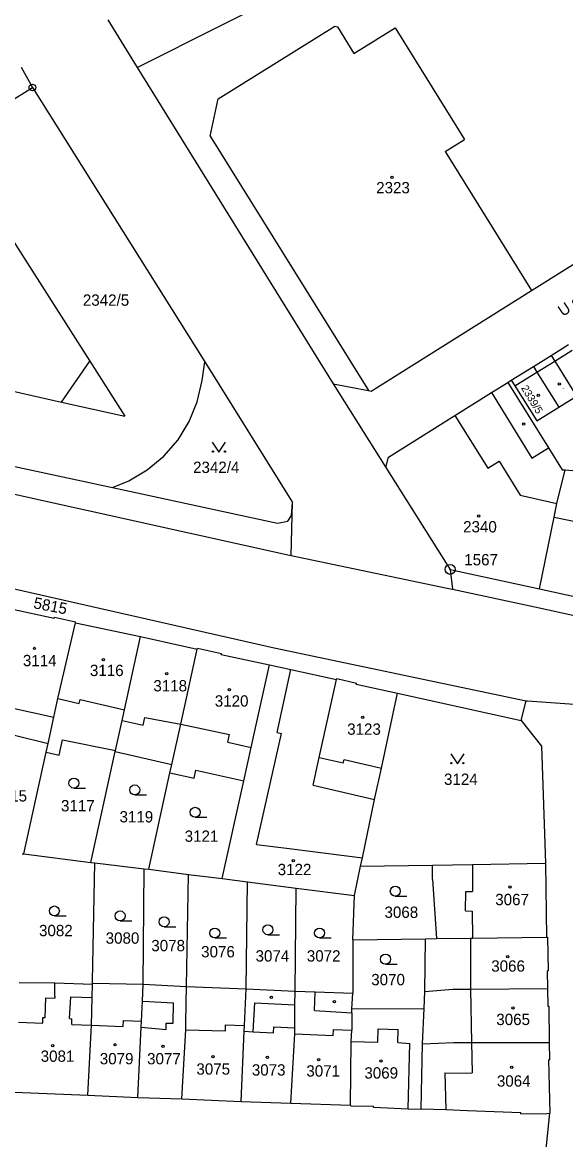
# Model space of a CAD drawing. Extents: x -735092 to -733385, y -1122435 to -1118992.
# Drawn here: x -734663.1 to -734581.5, y -1120137.2 to -1119969.3 of the extents above; entities that cross this region are included whole.
import ezdxf

# ---------------------------------------------------------------- set-up
doc = ezdxf.new("R2010")
doc.units = 0
for name, color, linetype in [('Vrstva 1', 7, 'Continuous'), ('Vrstva 15', 7, 'Continuous'), ('Vrstva 17', 7, 'Continuous'), ('Vrstva 18', 7, 'Continuous'), ('Vrstva 19', 7, 'Continuous'), ('Vrstva 25', 7, 'Continuous'), ('Vrstva 4', 7, 'Continuous')]:
    doc.layers.add(name, color=color, linetype=linetype)

msp = doc.modelspace()

# ---------------------------------------------------------------- linework, layer by layer
at = {"layer": 'Vrstva 1'}
for points in [[(-734645.81, -1119976.11), (-734620.71, -1119963.43)], [(-734650.22, -1119968.96), (-734645.81, -1119976.11)], [(-734633.69, -1119980.82), (-734616.17, -1119969.9)], [(-734616.17, -1119969.9), (-734615.74, -1119970.01)], [(-734615.74, -1119970.01), (-734613.33, -1119974.02)], [(-734610.02, -1119971.96), (-734607.12, -1119970.16)], [(-734607.12, -1119970.16), (-734596.72, -1119986.91)], [(-734613.33, -1119974.02), (-734610.02, -1119971.96)], [(-734586.64, -1120009.62), (-734530.99, -1119974.69)], [(-734663.22, -1119976.05), (-734661.56, -1119979.11)], [(-734645.81, -1119976.11), (-734642.09, -1119982.17)], [(-734665.37, -1119981.49), (-734661.56, -1119979.11)], [(-734661.56, -1119979.11), (-734635.69, -1120020.31)], [(-734642.09, -1119982.17), (-734616.43, -1120023.62)], [(-734634.88, -1119986.42), (-734633.69, -1119980.82)], [(-734634.88, -1119986.42), (-734611.09, -1120024.61)], [(-734599.58, -1119988.7), (-734596.72, -1119986.91)], [(-734599.58, -1119988.7), (-734586.64, -1120009.62)], [(-734668.88, -1119995.21), (-734652.92, -1120020.22)], [(-734610.72, -1120024.74), (-734586.64, -1120009.62)], [(-734583.7, -1120019.35), (-734581.09, -1120017.73)], [(-734759.44, -1120019.08), (-734622.96, -1120049.35)], [(-734586.37, -1120021.02), (-734583.7, -1120019.35)], [(-734583.7, -1120019.35), (-734583.17, -1120020.2)], [(-734652.92, -1120020.22), (-734647.67, -1120028.46)], [(-734636.09, -1120023.14), (-734635.69, -1120020.31)], [(-734635.69, -1120020.31), (-734622.54, -1120041.45)], [(-734589.68, -1120023.08), (-734586.37, -1120021.02)], [(-734586.37, -1120021.02), (-734585.84, -1120021.87)], [(-734583.17, -1120020.2), (-734579.89, -1120025.46)], [(-734585.84, -1120021.87), (-734582.56, -1120027.13)], [(-734667.8, -1120023.98), (-734657.17, -1120026.38)], [(-734636.81, -1120026.33), (-734636.09, -1120023.14)], [(-734616.43, -1120023.62), (-734611.09, -1120024.61)], [(-734616.43, -1120023.62), (-734608.52, -1120036.18)], [(-734592.65, -1120024.94), (-734590.18, -1120023.4)], [(-734590.18, -1120023.4), (-734589.68, -1120023.08)], [(-734590.18, -1120023.4), (-734584.08, -1120033.24)], [(-734589.68, -1120023.08), (-734589.15, -1120023.93)], [(-734589.15, -1120023.93), (-734585.87, -1120029.19)], [(-734712.66, -1120025.63), (-734649.52, -1120039.21)], [(-734611.09, -1120024.61), (-734610.72, -1120024.74)], [(-734598.14, -1120028.36), (-734592.65, -1120024.94)], [(-734582.56, -1120027.13), (-734579.89, -1120025.46)], [(-734657.17, -1120026.38), (-734647.67, -1120028.46)], [(-734638.05, -1120029.3), (-734636.81, -1120026.33)], [(-734585.87, -1120029.19), (-734582.56, -1120027.13)], [(-734639.68, -1120032.03), (-734638.05, -1120029.3)], [(-734608.13, -1120034.64), (-734598.14, -1120028.36)], [(-734641.82, -1120034.47), (-734639.68, -1120032.03)], [(-734644.33, -1120036.56), (-734641.82, -1120034.47)], [(-734584.08, -1120033.24), (-734582.04, -1120036.52)], [(-734608.52, -1120036.18), (-734608.13, -1120034.64)], [(-734608.52, -1120036.18), (-734599.31, -1120050.8)], [(-734647.1, -1120038.19), (-734644.33, -1120036.56)], [(-734582.86, -1120041.6), (-734581.6, -1120036.56)], [(-734582.04, -1120036.52), (-734581.6, -1120036.56)], [(-734581.6, -1120036.56), (-734569.64, -1120037.61)], [(-734649.52, -1120039.21), (-734647.1, -1120038.19)], [(-734649.52, -1120039.21), (-734624.77, -1120044.55)], [(-734622.73, -1120049.4), (-734622.54, -1120041.45)], [(-734622.69, -1120043.4), (-734622.54, -1120041.45)], [(-734583.27, -1120043.63), (-734582.86, -1120041.6)], [(-734624.77, -1120044.55), (-734623.21, -1120044.24)], [(-734623.21, -1120044.24), (-734622.69, -1120043.4)], [(-734585.45, -1120054.43), (-734583.27, -1120043.63)], [(-734622.96, -1120049.35), (-734622.73, -1120049.4)], [(-734622.73, -1120049.4), (-734599.31, -1120054.3)], [(-734683.27, -1120050.12), (-734625.28, -1120063.27)], [(-734599.31, -1120050.8), (-734598.87, -1120051.49)], [(-734598.87, -1120051.49), (-734585.45, -1120054.43)], [(-734598.87, -1120051.49), (-734598.52, -1120054.47)], [(-734599.31, -1120054.3), (-734598.52, -1120054.47)], [(-734598.52, -1120054.47), (-734586.13, -1120057.11)], [(-734585.45, -1120054.43), (-734561.99, -1120059.58)], [(-734664.74, -1120057.42), (-734658.29, -1120058.81)], [(-734586.13, -1120057.11), (-734553.31, -1120064.35)], [(-734658.29, -1120058.81), (-734658.25, -1120058.66)], [(-734658.25, -1120058.66), (-734655.07, -1120059.35)], [(-734657.73, -1120070.89), (-734655.1, -1120059.5)], [(-734655.1, -1120059.5), (-734655.07, -1120059.35)], [(-734655.1, -1120059.5), (-734645.32, -1120061.6)], [(-734647.73, -1120072.57), (-734645.32, -1120061.6)], [(-734645.32, -1120061.6), (-734636.82, -1120063.5)], [(-734639.3, -1120074.76), (-734636.82, -1120063.5)], [(-734636.82, -1120063.5), (-734636.79, -1120063.35)], [(-734636.79, -1120063.35), (-734633.18, -1120064.13)], [(-734633.21, -1120064.28), (-734633.18, -1120064.13)], [(-734633.21, -1120064.28), (-734625.98, -1120065.85)], [(-734625.28, -1120063.27), (-734587.43, -1120071.24)], [(-734628.06, -1120075.29), (-734625.98, -1120065.85)], [(-734625.98, -1120065.85), (-734622.75, -1120066.56)], [(-734622.75, -1120066.56), (-734615.9, -1120068.06)], [(-734618.5, -1120079.74), (-734615.9, -1120068.06)], [(-734615.9, -1120068.06), (-734615.87, -1120067.91)], [(-734615.87, -1120067.91), (-734612.93, -1120068.57)], [(-734612.97, -1120068.72), (-734612.93, -1120068.57)], [(-734612.97, -1120068.72), (-734606.76, -1120070.11)], [(-734658.35, -1120073.69), (-734657.73, -1120070.89)], [(-734609.15, -1120081.34), (-734606.76, -1120070.11)], [(-734606.76, -1120070.11), (-734588.2, -1120074.21)], [(-734588.2, -1120074.21), (-734587.43, -1120071.24)], [(-734587.43, -1120071.24), (-734587.27, -1120071.25)], [(-734587.27, -1120071.25), (-734572.48, -1120072.28)], [(-734648.09, -1120074.19), (-734647.73, -1120072.57)], [(-734659.21, -1120077.63), (-734658.35, -1120073.69)], [(-734649.09, -1120078.72), (-734648.09, -1120074.19)], [(-734640.64, -1120080.83), (-734639.3, -1120074.76)], [(-734588.2, -1120074.21), (-734585.16, -1120078.07)], [(-734668.96, -1120075.25), (-734659.21, -1120077.63)], [(-734628.71, -1120078.23), (-734628.06, -1120075.29)], [(-734659.5, -1120078.96), (-734659.21, -1120077.63)], [(-734657.54, -1120079.39), (-734657.04, -1120077.11)], [(-734657.04, -1120077.11), (-734649.09, -1120078.72)], [(-734585.16, -1120078.07), (-734584.53, -1120095.65)], [(-734662.86, -1120094.24), (-734659.5, -1120078.96)], [(-734659.5, -1120078.96), (-734657.54, -1120079.39)], [(-734652.78, -1120095.52), (-734649.12, -1120078.87)], [(-734649.12, -1120078.87), (-734649.09, -1120078.72)], [(-734649.12, -1120078.87), (-734640.64, -1120080.83)], [(-734629.82, -1120083.24), (-734628.71, -1120078.23)], [(-734619.43, -1120083.91), (-734618.5, -1120079.74)], [(-734640.91, -1120082.08), (-734640.64, -1120080.83)], [(-734610.19, -1120086.07), (-734609.15, -1120081.34)], [(-734644.1, -1120096.55), (-734640.91, -1120082.08)], [(-734640.91, -1120082.08), (-734637.28, -1120082.88)], [(-734637.28, -1120082.88), (-734637.02, -1120081.68)], [(-734637.02, -1120081.68), (-734629.82, -1120083.24)], [(-734633.07, -1120097.95), (-734629.82, -1120083.24)], [(-734619.43, -1120083.91), (-734610.19, -1120086.07)], [(-734612.02, -1120094.82), (-734610.19, -1120086.07)], [(-734663.11, -1120094.23), (-734662.86, -1120094.24)], [(-734662.86, -1120094.24), (-734652.78, -1120095.52)], [(-734612.29, -1120096.1), (-734612.02, -1120094.82)], [(-734652.78, -1120095.52), (-734652.19, -1120095.59)], [(-734652.53, -1120113.36), (-734652.19, -1120095.59)], [(-734652.19, -1120095.59), (-734644.76, -1120096.47)], [(-734644.93, -1120113.82), (-734644.76, -1120096.47)], [(-734644.76, -1120096.47), (-734644.1, -1120096.55)], [(-734644.1, -1120096.55), (-734638.11, -1120097.31)], [(-734613.2, -1120100.48), (-734612.29, -1120096.1)], [(-734612.29, -1120096.1), (-734601.52, -1120095.93)], [(-734601.53, -1120098.07), (-734601.52, -1120095.93)], [(-734601.52, -1120095.93), (-734595.52, -1120095.83)], [(-734595.52, -1120095.83), (-734584.53, -1120095.65)], [(-734584.53, -1120095.65), (-734584.4, -1120106.77)], [(-734638.44, -1120114.16), (-734638.11, -1120097.31)], [(-734638.11, -1120097.31), (-734633.07, -1120097.95)], [(-734633.07, -1120097.95), (-734629.26, -1120098.44)], [(-734601.53, -1120098.07), (-734600.93, -1120106.97)], [(-734629.48, -1120114.51), (-734629.26, -1120098.44)], [(-734629.26, -1120098.44), (-734624.27, -1120099.07)], [(-734624.27, -1120099.07), (-734621.99, -1120099.36)], [(-734622.13, -1120114.88), (-734621.99, -1120099.36)], [(-734621.99, -1120099.36), (-734613.2, -1120100.48)], [(-734613.47, -1120107.14), (-734613.2, -1120100.48)], [(-734613.47, -1120107.14), (-734602.57, -1120106.99)], [(-734613.47, -1120107.14), (-734613.47, -1120115.18)], [(-734602.67, -1120114.92), (-734602.57, -1120106.99)], [(-734602.57, -1120106.99), (-734600.93, -1120106.97)], [(-734600.93, -1120106.97), (-734595.81, -1120106.9)], [(-734595.81, -1120106.9), (-734595.5, -1120106.9)], [(-734595.5, -1120106.9), (-734584.4, -1120106.77)], [(-734584.4, -1120106.77), (-734584.26, -1120106.77)], [(-734584.26, -1120106.77), (-734584.17, -1120111.82)], [(-734652.54, -1120113.64), (-734652.53, -1120113.36)], [(-734584.32, -1120111.82), (-734584.26, -1120114.44)], [(-734584.32, -1120111.82), (-734584.17, -1120111.82)], [(-734663.52, -1120113.54), (-734658.19, -1120113.59)], [(-734658.19, -1120113.59), (-734652.54, -1120113.79)], [(-734652.58, -1120115.81), (-734652.54, -1120113.79)], [(-734652.54, -1120113.79), (-734652.54, -1120113.64)], [(-734652.54, -1120113.64), (-734644.93, -1120113.82)], [(-734645.05, -1120116.35), (-734644.93, -1120113.82)], [(-734644.93, -1120113.82), (-734638.44, -1120114.16)], [(-734638.47, -1120116.66), (-734638.44, -1120114.16)], [(-734638.44, -1120114.16), (-734629.48, -1120114.51)], [(-734629.73, -1120120.02), (-734629.48, -1120114.51)], [(-734629.48, -1120114.51), (-734622.13, -1120114.88)], [(-734622.15, -1120116.92), (-734622.13, -1120114.88)], [(-734622.13, -1120114.88), (-734619.14, -1120114.98)], [(-734619.14, -1120114.98), (-734613.47, -1120115.18)], [(-734602.78, -1120117.44), (-734602.67, -1120114.92)], [(-734602.67, -1120114.92), (-734598.45, -1120114.58)], [(-734598.45, -1120114.58), (-734595.79, -1120114.55)], [(-734595.79, -1120114.55), (-734584.26, -1120114.44)], [(-734584.26, -1120114.44), (-734584.2, -1120117.09)], [(-734652.66, -1120119.99), (-734652.58, -1120115.81)], [(-734645.19, -1120119.36), (-734645.05, -1120116.35)], [(-734638.51, -1120119.71), (-734638.47, -1120116.66)], [(-734613.62, -1120117.52), (-734613.47, -1120115.18)], [(-734622.18, -1120120.36), (-734622.15, -1120116.92)], [(-734613.63, -1120118.11), (-734613.62, -1120117.52)], [(-734613.63, -1120118.11), (-734613.61, -1120120.72)], [(-734613.62, -1120117.52), (-734602.78, -1120117.44)], [(-734603.01, -1120122.78), (-734602.78, -1120117.44)], [(-734584.2, -1120117.09), (-734584.05, -1120117.09)], [(-734584.05, -1120117.09), (-734583.98, -1120122.55)], [(-734653.23, -1120130.5), (-734652.66, -1120119.99)], [(-734645.23, -1120120.26), (-734645.19, -1120119.36)], [(-734638.52, -1120120.65), (-734638.51, -1120119.71)], [(-734629.77, -1120120.88), (-734629.73, -1120120.02)], [(-734645.73, -1120130.82), (-734645.23, -1120120.26)], [(-734639.14, -1120131.04), (-734638.52, -1120120.65)], [(-734630.24, -1120131.41), (-734629.77, -1120120.88)], [(-734622.77, -1120131.68), (-734622.19, -1120121.25)], [(-734622.19, -1120121.25), (-734622.18, -1120120.36)], [(-734613.69, -1120122.41), (-734613.61, -1120120.72)], [(-734613.81, -1120131.98), (-734613.69, -1120122.41)], [(-734603.19, -1120132.52), (-734603.01, -1120122.78)], [(-734603.01, -1120122.78), (-734598.31, -1120122.56)], [(-734598.31, -1120122.56), (-734595.67, -1120122.56)], [(-734595.67, -1120122.56), (-734583.98, -1120122.55)], [(-734583.98, -1120122.55), (-734583.94, -1120125.19)], [(-734584.08, -1120125.19), (-734583.88, -1120133.2)], [(-734584.08, -1120125.19), (-734583.94, -1120125.19)], [(-734664.23, -1120130.05), (-734653.23, -1120130.5)], [(-734653.23, -1120130.5), (-734645.73, -1120130.82)], [(-734645.73, -1120130.82), (-734639.14, -1120131.04)], [(-734639.14, -1120131.04), (-734630.24, -1120131.41)], [(-734630.24, -1120131.41), (-734622.77, -1120131.68)], [(-734622.77, -1120131.68), (-734613.81, -1120131.98)], [(-734613.81, -1120131.98), (-734613.76, -1120132.06)], [(-734613.76, -1120132.06), (-734610.36, -1120132.14)], [(-734610.37, -1120132.29), (-734610.36, -1120132.14)], [(-734610.37, -1120132.29), (-734605.18, -1120132.53)], [(-734605.18, -1120132.53), (-734603.19, -1120132.58)], [(-734603.19, -1120132.52), (-734599.51, -1120132.66)], [(-734603.19, -1120132.52), (-734603.19, -1120132.58)], [(-734599.51, -1120132.66), (-734596.23, -1120132.78)], [(-734596.23, -1120132.78), (-734588.23, -1120133.07)], [(-734588.24, -1120133.27), (-734588.23, -1120133.07)], [(-734588.24, -1120133.27), (-734584.36, -1120133.25)], [(-734585.56, -1120149.21), (-734583.88, -1120133.2)], [(-734584.36, -1120133.25), (-734583.88, -1120133.2)]]:
    msp.add_lwpolyline(points, dxfattribs=at)
at = {"layer": 'Vrstva 25'}
for points in [[(-734634.55, -1120032.4), (-734633.55, -1120033.9), (-734632.55, -1120032.4)], [(-734598.76, -1120079.21), (-734597.76, -1120080.71), (-734596.76, -1120079.21)], [(-734655.33, -1120084.35), (-734653.58, -1120084.35)], [(-734646.19, -1120085.37), (-734644.44, -1120085.37)], [(-734637.13, -1120088.74), (-734635.38, -1120088.74)], [(-734607.09, -1120100.59), (-734605.34, -1120100.59)], [(-734658.26, -1120103.56), (-734656.51, -1120103.56)], [(-734648.39, -1120104.3), (-734646.64, -1120104.3)], [(-734641.79, -1120105.18), (-734640.04, -1120105.18)], [(-734626.21, -1120106.38), (-734624.46, -1120106.38)], [(-734634.18, -1120106.87), (-734632.43, -1120106.87)], [(-734618.46, -1120106.87), (-734616.71, -1120106.87)], [(-734608.56, -1120110.8), (-734606.81, -1120110.8)]]:
    msp.add_lwpolyline(points, dxfattribs=at)
for centre, radius in [((-734661.56, -1119979.11), 0.499), ((-734661.56, -1119979.11), 0.0313), ((-734607.57, -1119992.61), 0.175), ((-734582.49, -1120023.63), 0.175), ((-734585.63, -1120025.37), 0.175), ((-734587.83, -1120029.67), 0.175), ((-734634.45, -1120033.8), 0.1), ((-734632.65, -1120033.8), 0.1), ((-734594.56, -1120043.47), 0.175), ((-734598.87, -1120051.49), 0.75), ((-734598.87, -1120051.49), 0.032), ((-734661.24, -1120063.38), 0.175), ((-734650.9, -1120065.04), 0.175), ((-734641.38, -1120067.17), 0.175), ((-734631.99, -1120069.56), 0.175), ((-734611.97, -1120073.72), 0.175), ((-734598.66, -1120080.61), 0.1), ((-734596.86, -1120080.61), 0.1), ((-734655.33, -1120083.6), 0.75), ((-734646.19, -1120084.62), 0.75), ((-734637.13, -1120087.99), 0.75), ((-734622.4, -1120095.23), 0.175), ((-734607.09, -1120099.84), 0.75), ((-734589.87, -1120099.2), 0.175), ((-734658.26, -1120102.81), 0.75), ((-734648.39, -1120103.55), 0.75), ((-734641.79, -1120104.43), 0.75), ((-734626.21, -1120105.63), 0.75), ((-734634.18, -1120106.12), 0.75), ((-734618.46, -1120106.12), 0.75), ((-734608.56, -1120110.05), 0.75), ((-734590.22, -1120109.67), 0.175), ((-734625.69, -1120115.79), 0.175), ((-734616.22, -1120116.45), 0.175), ((-734589.44, -1120117.38), 0.175), ((-734658.51, -1120123.05), 0.175), ((-734649.14, -1120122.92), 0.175), ((-734641.93, -1120123.16), 0.175), ((-734634.46, -1120124.71), 0.175), ((-734626.28, -1120124.78), 0.175), ((-734618.6, -1120125.14), 0.175), ((-734609.25, -1120125.34), 0.175), ((-734589.61, -1120126.29), 0.175)]:
    msp.add_circle(centre, radius, dxfattribs=at)
at = {"layer": 'Vrstva 4'}
for points in [[(-734583.17, -1120020.2), (-734580.56, -1120018.58)], [(-734657.17, -1120026.38), (-734652.92, -1120020.22)], [(-734585.84, -1120021.87), (-734583.17, -1120020.2)], [(-734589.15, -1120023.93), (-734585.84, -1120021.87)], [(-734592.65, -1120024.94), (-734586.61, -1120034.79)], [(-734598.14, -1120028.36), (-734593.18, -1120036.27)], [(-734586.61, -1120034.79), (-734584.08, -1120033.24)], [(-734593.18, -1120036.27), (-734591.49, -1120035.23)], [(-734591.49, -1120035.23), (-734588.35, -1120040.35)], [(-734588.35, -1120040.35), (-734582.86, -1120041.6)], [(-734583.27, -1120043.63), (-734577.16, -1120044.92)], [(-734624.84, -1120076), (-734622.75, -1120066.56)], [(-734657.73, -1120070.89), (-734654.52, -1120071.63)], [(-734654.52, -1120071.63), (-734654.38, -1120071.03)], [(-734654.38, -1120071.03), (-734647.73, -1120072.57)], [(-734668.15, -1120071.54), (-734658.35, -1120073.69)], [(-734648.09, -1120074.19), (-734644.91, -1120074.89)], [(-734644.91, -1120074.89), (-734644.66, -1120073.74)], [(-734644.66, -1120073.74), (-734639.3, -1120074.76)], [(-734639.3, -1120074.76), (-734631.96, -1120076.32)], [(-734632.21, -1120077.46), (-734631.96, -1120076.32)], [(-734627.92, -1120092.81), (-734624.19, -1120076.15)], [(-734624.84, -1120076), (-734624.19, -1120076.15)], [(-734632.21, -1120077.46), (-734628.71, -1120078.23)], [(-734618.5, -1120079.74), (-734614.89, -1120080.55)], [(-734614.89, -1120080.55), (-734614.78, -1120080.04)], [(-734614.78, -1120080.04), (-734609.15, -1120081.34)], [(-734627.92, -1120092.81), (-734623.04, -1120093.43)], [(-734623.04, -1120093.43), (-734612.02, -1120094.82)], [(-734595.52, -1120095.83), (-734595.51, -1120099.9)], [(-734596.54, -1120102.8), (-734596.48, -1120099.88)], [(-734596.48, -1120099.88), (-734595.51, -1120099.9)], [(-734596.54, -1120102.8), (-734595.56, -1120102.82)], [(-734595.56, -1120102.82), (-734595.5, -1120106.9)], [(-734595.81, -1120106.9), (-734595.79, -1120114.55)], [(-734658.2, -1120115.61), (-734658.19, -1120113.59)], [(-734619.24, -1120117.75), (-734619.14, -1120114.98)], [(-734595.79, -1120114.55), (-734595.67, -1120122.56)], [(-734659.65, -1120118.82), (-734659.53, -1120115.84)], [(-734659.53, -1120115.84), (-734658.19, -1120115.89)], [(-734658.2, -1120115.61), (-734658.19, -1120115.89)], [(-734655.97, -1120118.98), (-734655.81, -1120115.7)], [(-734655.81, -1120115.7), (-734652.58, -1120115.81)], [(-734645.05, -1120116.35), (-734640.38, -1120116.63)], [(-734640.42, -1120119.69), (-734640.38, -1120116.63)], [(-734628.42, -1120120.95), (-734628.19, -1120116.63)], [(-734628.19, -1120116.63), (-734622.15, -1120116.92)], [(-734619.24, -1120117.75), (-734613.63, -1120118.11)], [(-734663.63, -1120119.54), (-734660.01, -1120119.69)], [(-734660.01, -1120119.69), (-734659.97, -1120118.81)], [(-734659.97, -1120118.81), (-734659.65, -1120118.82)], [(-734655.97, -1120118.98), (-734655.63, -1120119)], [(-734655.66, -1120119.87), (-734655.63, -1120119)], [(-734655.66, -1120119.87), (-734652.66, -1120119.99)], [(-734652.66, -1120119.99), (-734647.93, -1120120.15)], [(-734647.93, -1120120.15), (-734647.9, -1120119.27)], [(-734647.9, -1120119.27), (-734645.19, -1120119.36)], [(-734641.5, -1120120.61), (-734641.49, -1120119.68)], [(-734641.49, -1120119.68), (-734640.42, -1120119.69)], [(-734632.58, -1120120.82), (-734632.55, -1120119.94)], [(-734632.55, -1120119.94), (-734629.73, -1120120.02)], [(-734645.23, -1120120.26), (-734641.5, -1120120.61)], [(-734638.52, -1120120.65), (-734632.58, -1120120.82)], [(-734629.77, -1120120.88), (-734628.42, -1120120.95)], [(-734628.42, -1120120.95), (-734625.35, -1120121.11)], [(-734625.35, -1120121.11), (-734625.31, -1120120.2)], [(-734625.31, -1120120.2), (-734622.18, -1120120.36)], [(-734622.19, -1120121.25), (-734616.41, -1120121.5)], [(-734616.41, -1120121.5), (-734616.37, -1120120.6)], [(-734616.37, -1120120.6), (-734613.61, -1120120.72)], [(-734609.71, -1120122.5), (-734609.65, -1120120.51)], [(-734609.65, -1120120.51), (-734606.67, -1120120.6)], [(-734606.73, -1120122.58), (-734606.67, -1120120.6)], [(-734613.69, -1120122.41), (-734609.71, -1120122.5)], [(-734606.73, -1120122.58), (-734604.91, -1120122.7)], [(-734605.18, -1120132.53), (-734604.91, -1120122.7)], [(-734595.67, -1120122.56), (-734595.54, -1120127.12)], [(-734599.64, -1120127.11), (-734599.51, -1120132.66)], [(-734599.64, -1120127.11), (-734596.46, -1120127.16)], [(-734596.46, -1120127.16), (-734595.54, -1120127.12)]]:
    msp.add_lwpolyline(points, dxfattribs=at)

# ---------------------------------------------------------------- texts
at = {"layer": 'Vrstva 15'}
msp.add_text('U spojky', height=1.7, rotation=33.70027, dxfattribs=at).set_placement((-734581.955, -1120013.573))
at = {"layer": 'Vrstva 17'}
msp.add_text('1567', height=1.7, dxfattribs=at).set_placement((-734596.74, -1120050.89))
at = {"layer": 'Vrstva 18'}
for s, p in [('2342/5', (-734653.98, -1120011.89)), ('2342/4', (-734637.44, -1120037.01)), ('3124', (-734599.78, -1120083.87)), ('3115', (-734667.42, -1120086.37)), ('3117', (-734657.26, -1120087.85)), ('3119', (-734648.48, -1120089.51)), ('3121', (-734638.7, -1120092.42)), ('3068', (-734608.71, -1120103.85)), ('3082', (-734660.56, -1120106.6)), ('3080', (-734650.56, -1120107.73)), ('3078', (-734643.71, -1120108.86)), ('3076', (-734636.23, -1120109.78)), ('3074', (-734628.06, -1120110.41)), ('3072', (-734620.37, -1120110.41)), ('3070', (-734610.7, -1120113.97))]:
    msp.add_text(s, height=1.7, dxfattribs=at).set_placement(p)
msp.add_text('5815', height=1.7, rotation=349.00278, dxfattribs=at).set_placement((-734661.486, -1120057.312))
at = {"layer": 'Vrstva 19'}
for s, height, p in [('2323', 1.7, (-734609.96, -1119995)), ('2339/4', 0.1, (-734582.06, -1120024.34)), ('2340', 1.7, (-734596.91, -1120045.94)), ('3114', 1.7, (-734662.98, -1120066.04)), ('3116', 1.7, (-734652.92, -1120067.52)), ('3118', 1.7, (-734643.4, -1120069.83)), ('3120', 1.7, (-734634.18, -1120072.11)), ('3123', 1.7, (-734614.31, -1120076.34)), ('3122', 1.7, (-734624.74, -1120097.43)), ('3067', 1.7, (-734592.09, -1120101.94)), ('3066', 1.7, (-734592.69, -1120111.93)), ('3065', 1.7, (-734591.93, -1120119.95)), ('3081', 1.7, (-734660.31, -1120125.47)), ('3079', 1.7, (-734651.44, -1120125.85)), ('3077', 1.7, (-734644.34, -1120125.85)), ('3075', 1.7, (-734636.94, -1120127.4)), ('3073', 1.7, (-734628.62, -1120127.54)), ('3071', 1.7, (-734620.44, -1120127.69)), ('3069', 1.7, (-734611.73, -1120127.99)), ('3064', 1.7, (-734591.84, -1120129.2))]:
    msp.add_text(s, height=height, dxfattribs=at).set_placement(p)
msp.add_text('2339/5', height=1.14, rotation=300.90239, dxfattribs=at).set_placement((-734588.246, -1120024.248))

doc.saveas('drawing.dxf')
